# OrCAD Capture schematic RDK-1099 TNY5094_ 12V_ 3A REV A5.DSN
size Custom; rev: B
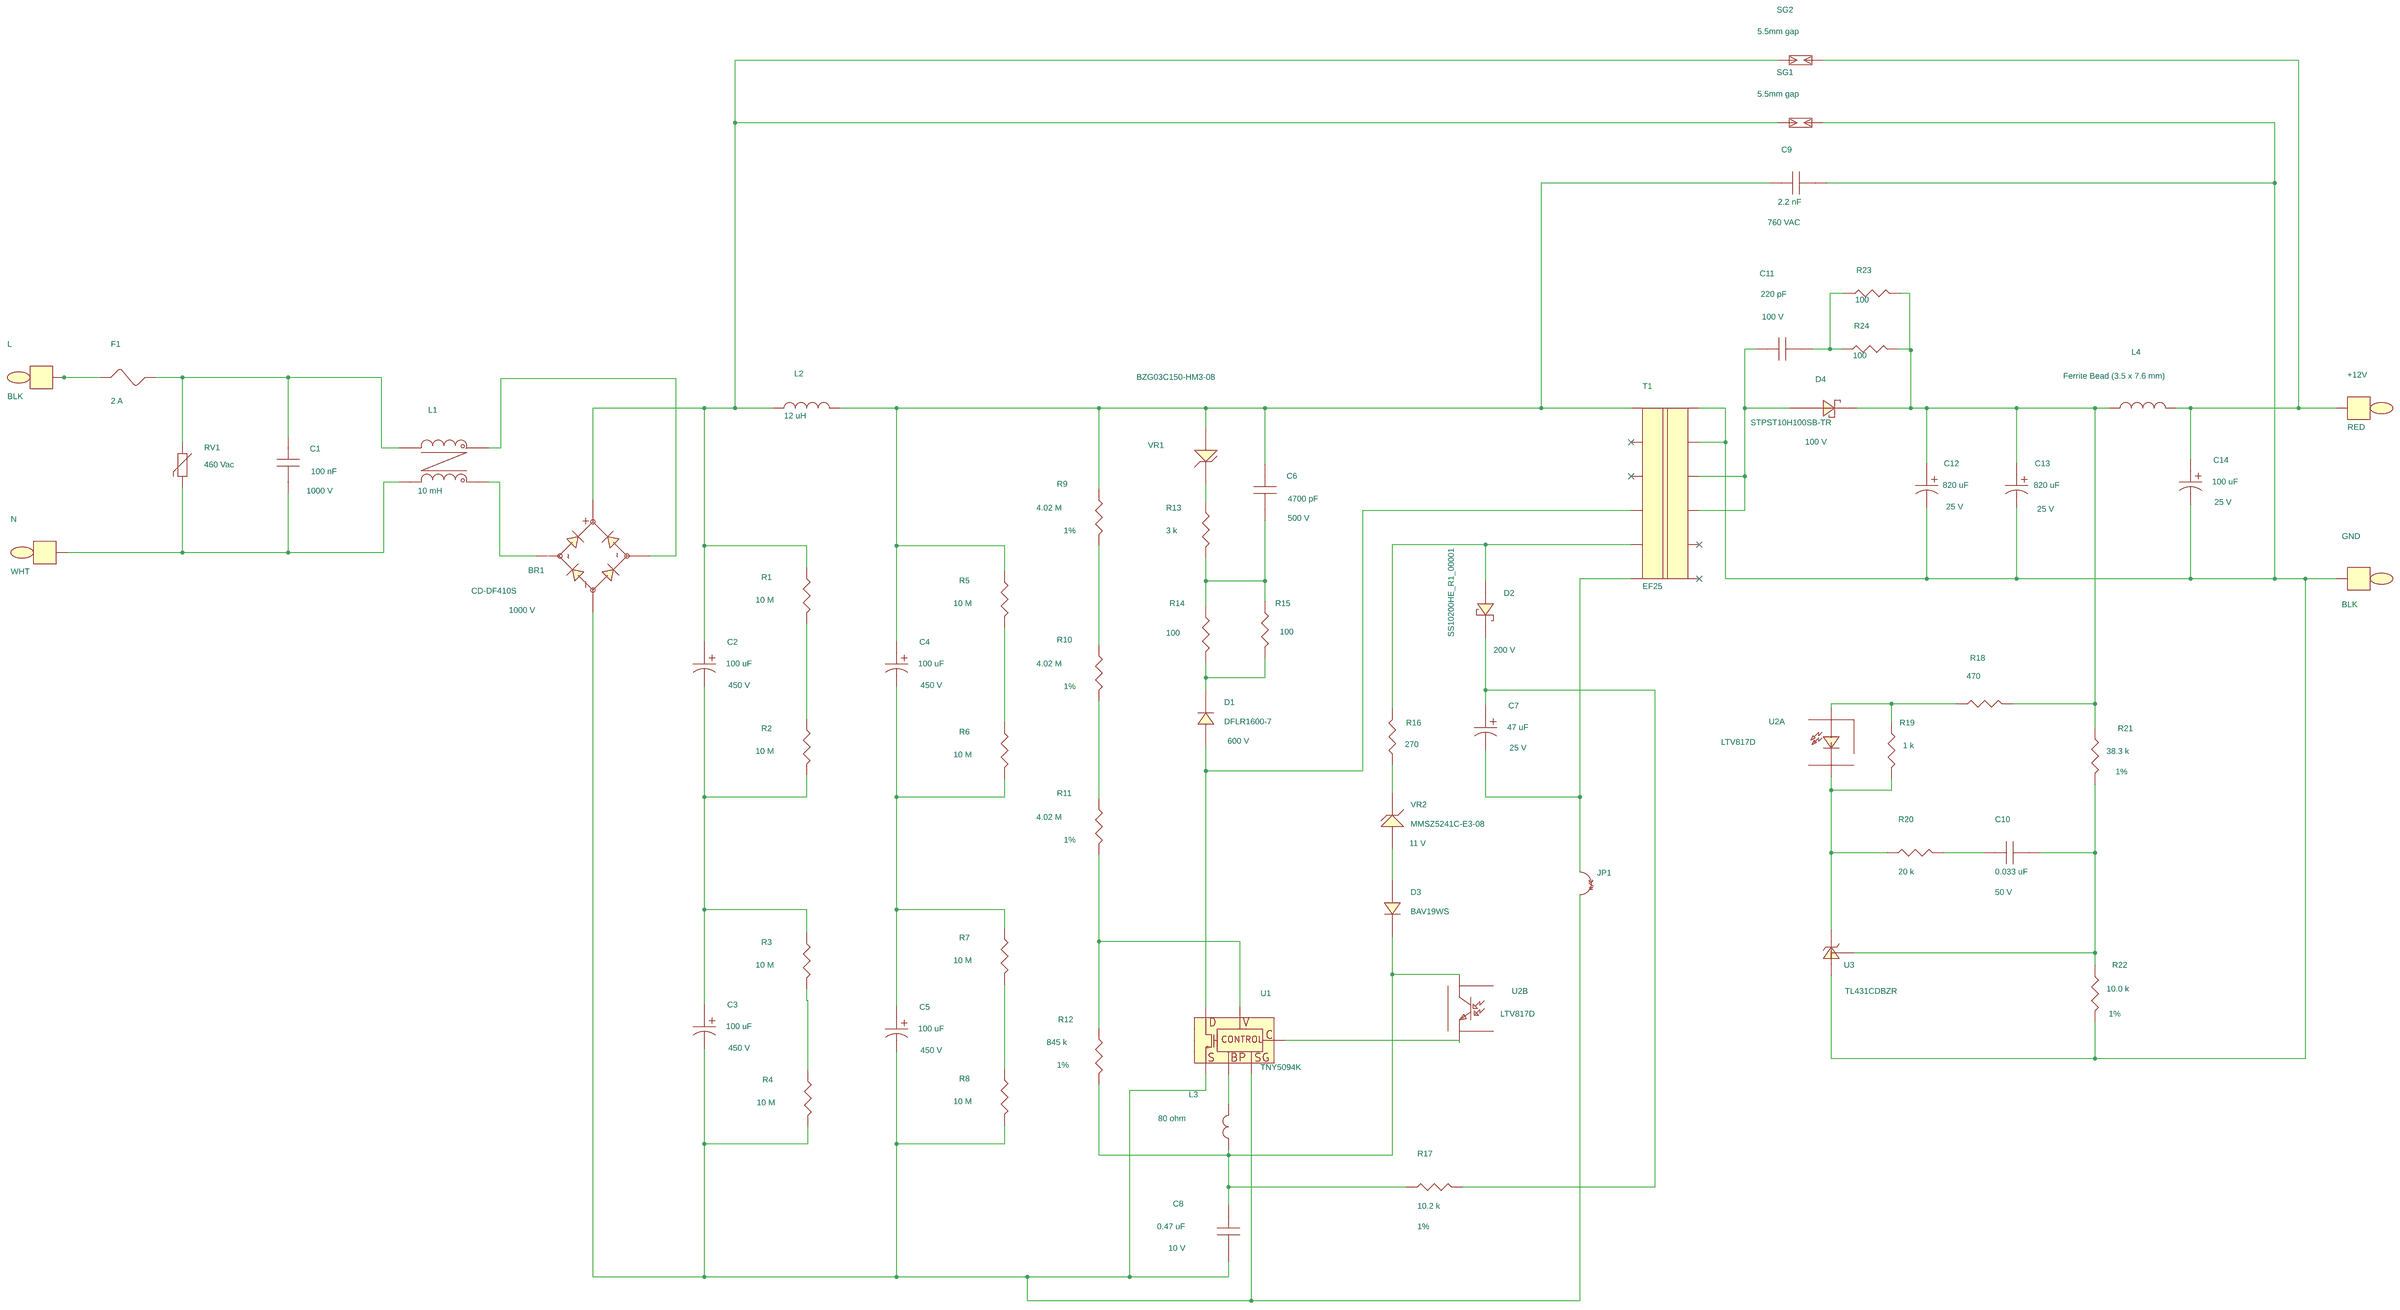
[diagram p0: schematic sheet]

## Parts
+12V  RED  [pitpkeystone125x125]
BR1  CD-DF410S  [CD-DF4xxS_BRN]
C1  100 nF  [pi_np_cap1045x415ls886d035]
C2  100 uF  [pipolcapclyd18ls7p5mmd040]
C3  100 uF  [pipolcapclyd18ls7p5mmd040]
C4  100 uF  [pipolcapclyd18ls7p5mmd040]
C5  100 uF  [pipolcapclyd18ls7p5mmd040]
C6  4700 pF  [pismc1206]
C7  47 uF  [pipolcapclyd200ls80030]
C8  0.47 uF  [pismc0805]
C9  2.2 nF  [pinpycaprad540x290ls400040]
C10  0.033 uF  [pismc0603]
C11  220 pF  [pismc0805]
C12  820 uF  [pipolcapclyd10mm040]
C13  820 uF  [pipolcapclyd10mm040]
C14  100 uF  [pipolcapcyld250ls100030]
D1  DFLR1600-7  [pismddflr120012]
D2  SS10200HE_R1_00001  [pi_sm_sod-123HE]
D3  BAV19WS  [pismsod323]
D4  STPST10H100SB-TR  [pi_sm_to252_dpak]
F1  2 A  [pi_rst_microfuse]
GND  BLK  [pitpkeystone125x125]
JP1  J  [pi_jumper400]
L  BLK  [pitpkeystone125x125]
L1  10 mH  [pi_toroid_balun_1]
L2  12 uH  [pi_choke_coilcraft_rfb1010]
L3  80 ohm  [pismr0805]
L4  Ferrite Bead (3.5 x 7.6 mm)  [pi12wresd180ls675d040]
N  WHT  [pitpkeystone125x125]
R1  10 M  [pismr1206]
R2  10 M  [pismr1206]
R3  10 M  [pismr1206]
R4  10 M  [pismr1206]
R5  10 M  [pismr1206]
R6  10 M  [pismr1206]
R7  10 M  [pismr1206]
R8  10 M  [pismr1206]
R9  4.02 M  [pi14wresd100ls400d030]
R10  4.02 M  [pi14wresd100ls400d030]
R11  4.02 M  [pi14wresd100ls400d030]
R12  845 k  [pismr0603]
R13  3 k  [pismr1206]
R14  100  [pismr1206]
R15  100  [pismr1206]
R16  270  [pismr1206]
R17  10.2 k  [pismr0603]
R18  470  [pismr1206]
R19  1 k  [pismr0603]
R20  20 k  [pismr0603]
R21  38.3 k  [pismr1206]
R22  10.0 k  [pismr1206]
R23  100  [pismr1206]
R24  100  [pismr1206]
RV1  460 Vac  [pidisc675x225ls335x140040]
SG1  5.5mm gap  [PI_SPARK_GAP_5p5MM]
SG2  5.5mm gap  [PI_SPARK_GAP_5p5MM]
T1  EF25  [pi_bobbin_ef25_h_12p]
U1  TNY5094K  [pi_ic_smd_esop_11-12p_short7-12]
U2  LTV817D  [pi_dip4]  (sections A,B)
U3  TL431CDBZR  [pismsot23123_1]
VR1  BZG03C150-HM3-08  [pismdo214ac12]
VR2  MMSZ5241C-E3-08  [pi_sm_sod-123_12]

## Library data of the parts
+12V = TESTPOINT: ALT_SYMBOLS: TP_5010-14; FPLIST: pitpkeystone125x125,TP_5010-14; Part Number: 35-00043-00
BR1 = DIODE_BRIDGE_+~~-: Disp_Voltage: 1000 V; Part Number: 15-02002-00
C1 = CAP_NP: Disp_Voltage: 1000 V; Part Number: 20-08735-00; Voltage: 1000 V
C2-C5 = CAP_POL: ALT_SYMBOLS: pipolcapclyd18ls7p5h25mmd040; Disp_Voltage: 450 V; FPLIST: pipolcapclyd18ls7p5mmd040,pipolcapclyd18ls7p5h25mmd040; Part Number: 20-01593-00; Voltage: 450 V
C6 = CAP_NP: Disp_Voltage: 500 V; PCB Editor PCBFP: pinpcaprad500x200400030; Part Number: 20-01417-00; Tol: 20; Voltage: 500 V
C7 = CAP_POL: ALT_SYMBOLS: pipolcapclyd200ls80030h; Disp_Voltage: 25 V; FPLIST: pipolcapclyd200ls80030,pipolcapclyd200ls80030h; Part Number: 20-00026-00; Voltage: 25 V
C8 = CAP_NP: ALT_SYMBOLS: Unisem_RMCF0805UL; Disp_Voltage: 10 V; FPLIST: pismc0805,Unisem_RMCF0805UL; Part Number: 20-01687-00; Voltage: 10 V
C9 = CAP_NP: Disp_Voltage: 760 VAC; Part Number: 20-01427-00; Voltage: 760 VAC
C10 = CAP_NP: ALT_SYMBOLS: Unisem_RMCF0603UL,pismc0603_1; Disp_Voltage: 50 V; FPLIST: pismc0603,Unisem_RMCF0603UL,pismc0603_1; Part Number: 20-09224-00; Voltage: 50 V
C11 = CAP_NP: ALT_SYMBOLS: Unisem_RMCF0805UL; Disp_Voltage: 100 V; Part Number: 20-00580-00; Voltage: 100 V
C12 = CAP_POL: ALT_SYMBOLS: pipolcapcyld400ls2000401000h; Disp_Voltage: 25 V; FPLIST: pipolcapcyld400ls200040,pipolcapcyld400ls2000401000h; Part Number: 20-00034-00; Voltage: 25 V
C13 = CAP_POL: ALT_SYMBOLS: pipolcapcyld400ls2000401000h; Disp_Voltage: 25 V; FPLIST: pipolcapclyd10mm040,pipolcapcyld400ls2000401000h; Part Number: 20-00034-00; Voltage: 25 V
C14 = CAP_POL: ALT_SYMBOLS: pipolcapcyld250ls100030h; Disp_Voltage: 25 V; FPLIST: pipolcapcyld250ls100030,pipolcapcyld250ls100030h; Part Number: 20-00027-00; Voltage: 25 V
D1 = DIODE: Disp_Voltage: 600 V; Part Number: 15-00826-00
D2 = DIODE_SCHOTTKY: Disp_Voltage: 200 V; Part Number: 15-01774-00
D3 = DIODE: ALT_SYMBOLS: SOD323_UL_IPC,pismsod323_1; FPLIST: pismsod323,SOD323_UL_IPC,pismsod323_1; Part Number: 15-00658-00
D4 = DIODE_SCHOTTKY_DPAK_AKA: Disp_Voltage: 100 V; Part Number: 15-02212-00
F1 = FUSE: ALT_SYMBOLS: pirstmicrofusehoz; FPLIST: pi_rst_microfuse,pirstmicrofusehoz; Part Number: 40-00021-00
GND L = TESTPOINT: ALT_SYMBOLS: TP_5010-14; FPLIST: pitpkeystone125x125,TP_5010-14; Part Number: 35-00042-00
JP1 = JUMPER_2: Part Number: 65-00003-00
L1 = TORRID_4P_12_34: Part Number: 32-00016-00
L2 = INDUCTOR: Part Number: 30-00482-00
L3 = INDUCTOR_BEAD_2: Part Number: 30-00635-00
L4 = INDUCTOR: ALT_SYMBOLS: pi12wvresd180ls150d040,pi12wvresd180ls200d040,pi12wvresd180ls250d040; FPLIST: pi12wresd180ls675d040,pi12wvresd180ls150d040,pi12wvresd180ls200d040,pi12wvresd180ls250d040; GROUP: 2; Part Number: 30-00070-00; Tol: 0.1
N = TESTPOINT: Part Number: 35-00044-00
R1-R8 = R: Part Number: 05-01445-00
R9-R11 = R: ALT_SYMBOLS: pi14wvresd100ls125d030,pi14wvresd100ls150d030,pi14wvresd100ls200d030,pi14wvresd100ls300d030,pi14wresd100ls400d030,pi14wresd100ls500d030; Disp_Tol: 1%; FPLIST: pi14wvresd100ls100d030,pi14wvresd100ls125d030,pi14wvresd100ls150d030,pi14wvresd100ls200d030,pi14wvresd100ls300d030,pi14wresd100ls400d030,pi14wresd100ls500d030; Part Number: 05-06448-00
R12 = R: ALT_SYMBOLS: Unisem_RMCF0603UL; Disp_Tol: 1%; FPLIST: pismr0603,Unisem_RMCF0603UL; Part Number: 05-01263-00
R13 = R: PCB Editor PCBFP: pi12wvresd180ls150d040,pi12wvresd180ls200d040,pi12wvresd180ls250d040,pi12wresd180ls675d040; Part Number: 05-01363-00
R14 R15 R23 R24 = R: Part Number: 05-01328-00
R16 = R: Part Number: 05-01338-00
R17 = R: ALT_SYMBOLS: Unisem_RMCF0603UL; Disp_Tol: 1%; FPLIST: pismr0603,Unisem_RMCF0603UL; Part Number: 05-03183-00
R18 = R: GROUP: 2; PCB Editor PCBFP: pismr0805; Part Number: 05-01344-00; Tol: 5%
R19 = R: ALT_SYMBOLS: Unisem_RMCF0603UL; FPLIST: pismr0603,Unisem_RMCF0603UL; Part Number: 05-01688-00
R20 = R: ALT_SYMBOLS: Unisem_RMCF0603UL; FPLIST: pismr0603,Unisem_RMCF0603UL; Part Number: 05-01719-00
R21 = R: Disp_Tol: 1%; Part Number: 05-00345-00
R22 = R: Disp_Tol: 1%; Part Number: 05-00289-00
RV1 = VARISTOR: Part Number: 85-00016-00
SG1 SG2 = SPARK_GAP: Part Number: 66-00357-00
T1 = BEI30_12P_GENERIC: Part Number: 25-00882-00
U1 = TinySwitch-5K: Part Number: 10-01663-00
U2 = OPTO_A_B: Part Number: 53-00019-00
U3 = TL431CDBZR: Part Number: 45-00492-00
VR1 = DIODE_ZENER: Part Number: 15-01589-00
VR2 = DIODE_ZENER: Disp_Voltage: 11 V; Part Number: 15-01690-00

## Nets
N232812: BR1.4 C3.2 C5.2 C8.2 JP1.2 R4.2 R8.2 U1.4 U1.7
N233356: +12V.1 C14.1 L4.1 SG2.2
N233758: C6.2 R13.2 R14.1 R15.1
N234018: BR1.1 C2.1 L2.1 R1.1 SG1.1 SG2.1
N234026: C9.2 C12.2 C13.2 C14.2 GND.1 R22.2 SG1.2 T1.7 T1.8 U3.3(A)
N234356: C12.1 C13.1 D4.2 L4.2 R18.2 R21.1 R23.2 R24.2
N234408: C10.2 R21.2 R22.1 U3.2(VREF)
N274025: C7.2 JP1.1 T1.1
N361695: C7.1 D2.1 R17.2
N9221700: D2.2 R16.2 T1.2
N9273985: C1.1 F1.2 L1.4 RV1.1
N9299708: C4.1 C6.1 C9.1 L2.2 R5.1 R9.1 T1.6 VR1.2
N9317049: C1.2 L1.2 N.1 RV1.2
N9342481: R18.1 R19.1 U2.1(A)
N9436307: C11.2 R23.1 R24.1
N9436321: C11.1 D4.1 T1.9 T1.10
N9446382: C10.1 R20.2
N9464475: R19.2 R20.1 U2.2(C) U3.1(C)
N9467610: BR1.3 L1.3
N9469611: D1.2(A) T1.3 U1.6
N9474130: F1.1 L.1
N9474318: BR1.2 L1.1
N9474875: D1.1(K) R14.2 R15.2
N9485927: C8.1 D3.1(K) L3.1 R12.2 R17.1 U2.4(C)
N9515325: R11.2 R12.1 U1.1
N9531791: R9.2 R10.1
N9533645: U1.3 U2.3(E)
N9537521: R13.1 VR1.1
N9539308: D3.2(A) VR2.2
N9555264: R16.1 VR2.1
N9562271: C2.2 C3.1 R2.2 R3.1
N9562449: R1.2 R2.1
N9562513: R3.2 R4.1
N9562701: C4.2 C5.1 R6.2 R7.1
N9562746: R5.2 R6.1
N9562772: R7.2 R8.1
N9566319: R10.2 R11.1
N9594123: L3.2 U1.2

Not connected (* = marked no-connect by the designer): D4 3; T1 4* 5* 11* 12*; U1 8 9 10 11 12
